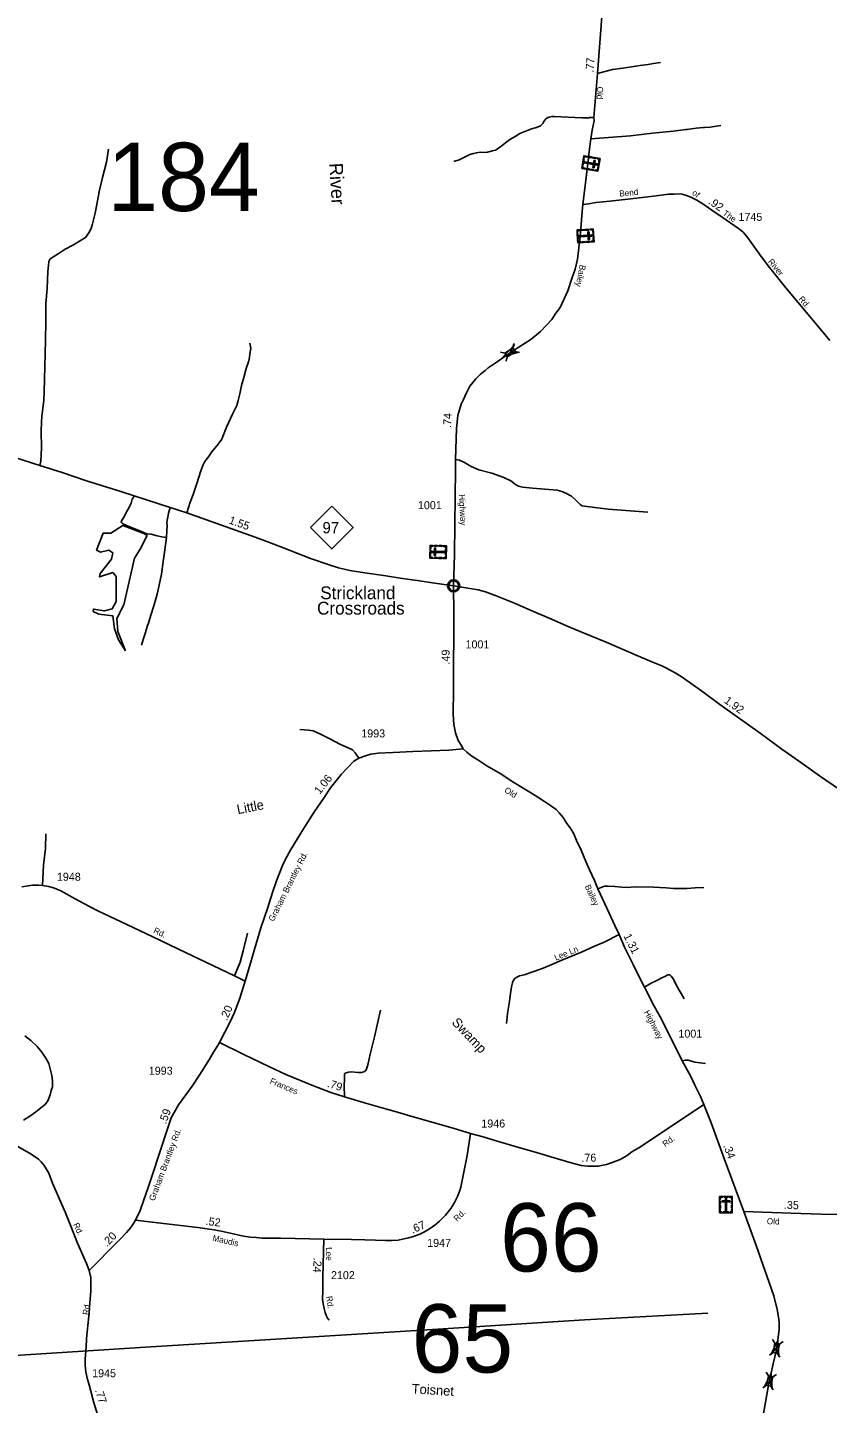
# Model space of a CAD drawing. Extents: x 2220236 to 2384410, y 720751 to 894131.
# Drawn here: x 2285908 to 2298391, y 754902 to 776386 of the extents above; entities that cross this region are included whole.
import ezdxf

# ---------------------------------------------------------------- set-up
doc = ezdxf.new("R2010")
doc.units = 0
doc.layers.add('Default', color=7, linetype='Continuous')

msp = doc.modelspace()

# ---------------------------------------------------------------- linework, layer by layer
at = {"layer": 'Default'}
for p, q in [((2296179, 774794), (2296182, 774794)), ((2296182, 774794), (2296199, 774796)), ((2296199, 774796), (2296201, 774796)), ((2296455, 774824), (2296457, 774824)), ((2296457, 774824), (2296468, 774825)), ((2296468, 774825), (2296471, 774825)), ((2293287, 771316), (2293355, 771302)), ((2293481, 771384), (2293496, 771452)), ((2293519, 771326), (2293587, 771312)), ((2293379, 771175), (2293393, 771243)), ((2297572, 755844), (2297534, 755901)), ((2297640, 755830), (2297697, 755868)), ((2297484, 755657), (2297542, 755696)), ((2297649, 755624), (2297611, 755681)), ((2297380, 755148), (2297438, 755186)), ((2297470, 755334), (2297432, 755391)), ((2297537, 755320), (2297595, 755357)), ((2297545, 755114), (2297507, 755171))]:
    msp.add_line(p, q, dxfattribs=at)
for points in [[(2294572, 773621), (2294615, 773960), (2294663, 774351), (2294685, 774533), (2294700, 774646), (2294721, 774782), (2294748, 774928), (2294747, 774982), (2294801, 775666), (2294954, 777657)], [(2294801, 775666), (2295036, 775729), (2295196, 775754), (2295468, 775795), (2295591, 775810), (2295677, 775825), (2295787, 775839)], [(2292559, 774292), (2292641, 774321), (2292812, 774402), (2292868, 774421), (2292913, 774431), (2292975, 774440), (2293037, 774436), (2293087, 774441), (2293161, 774463), (2293209, 774472), (2293257, 774503), (2293320, 774547), (2293435, 774638), (2293517, 774687), (2293592, 774730), (2293772, 774803), (2293849, 774826), (2293911, 774852), (2293948, 774887), (2293964, 774921), (2293998, 774959), (2294014, 774973), (2294032, 774983), (2294048, 774986), (2294090, 774996), (2294110, 774998), (2294126, 774996), (2294560, 774977), (2294588, 774977), (2294600, 774975), (2294634, 774975), (2294650, 774973), (2294666, 774977), (2294678, 774983), (2294747, 774982)], [(2294700, 774646), (2295316, 774696), (2295659, 774735), (2295983, 774770), (2296179, 774794)], [(2296201, 774796), (2296232, 774800), (2296340, 774815), (2296455, 774824)], [(2296471, 774825), (2296559, 774832), (2296729, 774859)], [(2286097, 769550), (2286117, 769613), (2286127, 769820), (2286118, 770088), (2286125, 770226), (2286132, 770318), (2286148, 770437), (2286162, 770568), (2286169, 770700), (2286174, 770899), (2286178, 771090), (2286183, 771298), (2286188, 771504), (2286193, 771797), (2286195, 772078), (2286214, 772314), (2286226, 772579), (2286233, 772675), (2286239, 772729), (2286255, 772767), (2286286, 772790), (2286319, 772809), (2286387, 772851), (2286497, 772926), (2286626, 772993), (2286745, 773064), (2286813, 773109), (2286865, 773179), (2286902, 773247), (2286923, 773320), (2286961, 773490), (2287033, 773846), (2287078, 774046), (2287138, 774283), (2287172, 774489)], [(2298428, 771502), (2298252, 771715), (2297740, 772321), (2297574, 772532), (2297464, 772666), (2297332, 772847), (2297148, 773105), (2297109, 773156), (2297069, 773198), (2297002, 773247), (2296750, 773424), (2296587, 773532), (2296444, 773633), (2296396, 773664), (2296353, 773691), (2296310, 773712), (2296259, 773736), (2296193, 773763), (2296123, 773784), (2296062, 773789), (2296001, 773787), (2295912, 773786), (2295718, 773759), (2295324, 773714), (2294994, 773677), (2294776, 773654), (2294668, 773635), (2294572, 773621)], [(2293362, 771255), (2293562, 771392), (2293762, 771516), (2293911, 771641), (2294007, 771739), (2294089, 771830), (2294153, 771926), (2294218, 772017), (2294338, 772273), (2294404, 772466), (2294455, 772615), (2294488, 772772), (2294532, 773123), (2294553, 773378), (2294563, 773512), (2294572, 773621)], [(2288394, 768809), (2288422, 768891), (2288446, 768975), (2288490, 769096), (2288547, 769267), (2288612, 769463), (2288641, 769546), (2288676, 769609), (2288732, 769685), (2288783, 769762), (2288880, 769881), (2288938, 769959), (2288957, 770003), (2289011, 770144), (2289107, 770350), (2289172, 770487), (2289194, 770562), (2289219, 770668), (2289249, 770799), (2289282, 770923), (2289320, 771064), (2289357, 771169), (2289371, 771236), (2289379, 771290), (2289390, 771375), (2289379, 771459)], [(2292557, 767669), (2292569, 768152), (2292576, 768630), (2292581, 769037), (2292586, 769500), (2292588, 769642), (2292600, 770127), (2292623, 770328), (2292647, 770418), (2292675, 770507), (2292706, 770569), (2292759, 770682), (2292810, 770784), (2292902, 770899), (2292972, 770971), (2293047, 771032), (2293096, 771074), (2293204, 771146), (2293258, 771184), (2293305, 771215), (2293362, 771255)], [(2284719, 769987), (2285579, 769716), (2286097, 769550), (2286448, 769441), (2286829, 769308), (2287362, 769142), (2287570, 769072), (2288135, 768892), (2288394, 768809), (2289461, 768428), (2289685, 768344), (2289978, 768231), (2290325, 768095), (2290629, 767992), (2290758, 767950), (2290938, 767908), (2291170, 767873), (2291498, 767826), (2291724, 767791), (2291990, 767752), (2292265, 767711), (2292557, 767669)], [(2292588, 769642), (2292651, 769631), (2292724, 769596), (2292831, 769530), (2292951, 769479), (2293152, 769430), (2293342, 769360), (2293448, 769306), (2293523, 769250), (2293570, 769224), (2293633, 769210), (2293790, 769193), (2294174, 769161), (2294247, 769142), (2294307, 769116), (2294396, 769067), (2294481, 768992), (2294532, 768939), (2294565, 768918), (2294635, 768909), (2294970, 768866), (2295586, 768821)], [(2287570, 769072), (2287556, 769043), (2287540, 769022), (2287523, 768962), (2287505, 768920), (2287486, 768882), (2287469, 768852), (2287408, 768743), (2287369, 768675), (2287373, 768656), (2287394, 768637), (2287478, 768598), (2287607, 768546), (2287706, 768508), (2287771, 768483), (2287837, 768474), (2287928, 768448), (2288003, 768434), (2288074, 768424)], [(2288074, 768424), (2288080, 768529), (2288085, 768604), (2288083, 768652), (2288088, 768694), (2288099, 768743), (2288109, 768803), (2288125, 768857), (2288135, 768892)], [(2287436, 766655), (2287319, 766956), (2287299, 767158), (2287410, 767371), (2287579, 768103), (2287667, 768240), (2287772, 768453), (2287723, 768485), (2287394, 768610), (2287209, 768493), (2287088, 768493), (2286984, 768228), (2287048, 768196), (2287177, 768228), (2287241, 768184), (2287217, 768083), (2287040, 767862), (2287032, 767809), (2287237, 767878), (2287289, 767817), (2287292, 767422), (2287229, 767310), (2287108, 767278), (2286935, 767306), (2286931, 767270), (2287020, 767226), (2287239, 767198), (2287267, 766997), (2287327, 766824), (2287436, 766655)], [(2287685, 766743), (2287715, 766846), (2287748, 766939), (2287765, 767000), (2287779, 767047), (2287793, 767085), (2287834, 767212), (2287877, 767354), (2287929, 767539), (2287964, 767678), (2287996, 767853), (2288024, 768048), (2288052, 768233), (2288074, 768424)], [(2292707, 765123), (2292675, 765181), (2292630, 765256), (2292585, 765371), (2292560, 765505), (2292550, 765666), (2292553, 766043), (2292557, 766307), (2292557, 766558), (2292558, 766773), (2292562, 766967), (2292558, 767237), (2292557, 767669)], [(2292557, 767669), (2292941, 767604), (2293056, 767573), (2293221, 767515), (2293508, 767398), (2293766, 767286), (2294048, 767166), (2294357, 767030), (2294680, 766895), (2294935, 766787), (2295443, 766572), (2295676, 766474), (2295805, 766420), (2295870, 766387), (2295938, 766354), (2296015, 766310), (2296109, 766252), (2296423, 766028), (2296712, 765816), (2297339, 765367), (2297679, 765120), (2297992, 764902), (2298265, 764703), (2298578, 764488)], [(2290159, 765425), (2290290, 765416), (2290365, 765406), (2290477, 765352), (2290623, 765280), (2290791, 765193), (2290903, 765144), (2290979, 765107), (2291021, 765062), (2291079, 764977)], [(2289304, 761495), (2289550, 762328), (2289657, 762647), (2289730, 762883), (2289791, 763061), (2289884, 763302), (2289931, 763403), (2290018, 763551), (2290215, 763876), (2290384, 764145), (2290524, 764347), (2290636, 764515), (2290803, 764725), (2290894, 764823), (2291000, 764930), (2291079, 764977), (2291196, 765019), (2291267, 765042), (2291379, 765056), (2291613, 765069), (2291920, 765083), (2292204, 765093), (2292483, 765104), (2292707, 765123)], [(2296461, 759572), (2296407, 759695), (2296373, 759767), (2296322, 759870), (2296257, 760008), (2296125, 760251), (2295805, 760891), (2295680, 761115), (2295533, 761403), (2295467, 761535), (2295359, 761754), (2295221, 762029), (2295139, 762223), (2295071, 762366), (2294954, 762623), (2294809, 762939), (2294755, 763068), (2294685, 763222), (2294619, 763365), (2294549, 763540), (2294472, 763694), (2294431, 763799), (2294373, 763890), (2294326, 763959), (2294265, 764052), (2294206, 764127), (2294157, 764176), (2294068, 764237), (2293973, 764303), (2293869, 764370), (2293745, 764448), (2293499, 764597), (2293281, 764736), (2293075, 764859), (2292934, 764952), (2292839, 765011), (2292763, 765073), (2292707, 765123)], [(2286143, 762992), (2286158, 763306), (2286187, 763570), (2286193, 763799)], [(2289304, 761495), (2289135, 761581), (2288373, 761944), (2287865, 762186), (2287270, 762469), (2287013, 762590), (2286862, 762666), (2286649, 762779), (2286425, 762909), (2286327, 762950), (2286239, 762973), (2286143, 762992), (2286079, 762995), (2285985, 762995), (2285817, 762967)], [(2294809, 762939), (2294912, 762978), (2294968, 762978), (2295074, 762975), (2295184, 762964), (2295264, 762961), (2295322, 762964), (2295398, 762970), (2295678, 762965), (2295872, 762955), (2295986, 762944), (2296198, 762942), (2296324, 762951), (2296460, 762956)], [(2289135, 761581), (2289224, 761791), (2289272, 761971), (2289338, 762244)], [(2293383, 760833), (2293398, 760989), (2293422, 761147), (2293437, 761269), (2293462, 761409), (2293475, 761471), (2293485, 761501), (2293514, 761537), (2293542, 761558), (2293584, 761580), (2293658, 761593), (2293811, 761646), (2293953, 761700), (2294090, 761757), (2294243, 761824), (2294562, 761953), (2294745, 762037), (2294904, 762104), (2295139, 762223)], [(2288903, 760539), (2288989, 760702), (2289067, 760851), (2289139, 761005), (2289221, 761231), (2289304, 761495)], [(2295533, 761403), (2295642, 761463), (2295728, 761508), (2295805, 761548), (2295851, 761570), (2295901, 761593), (2295931, 761595), (2295954, 761572), (2295987, 761525), (2296027, 761448), (2296078, 761355), (2296106, 761301), (2296156, 761219)], [(2290854, 759691), (2290850, 759860), (2290856, 759972), (2290856, 760028), (2290856, 760050), (2290866, 760059), (2290918, 760076), (2290960, 760079), (2291065, 760071), (2291117, 760072), (2291157, 760080), (2291181, 760096), (2291197, 760122), (2291222, 760208), (2291255, 760355), (2291320, 760625), (2291416, 761044)], [(2285864, 760642), (2285959, 760567), (2286056, 760474), (2286131, 760385), (2286194, 760293), (2286240, 760208), (2286288, 760022), (2286297, 759936), (2286298, 759848), (2286278, 759788), (2286261, 759720), (2286222, 759630), (2286181, 759569), (2286117, 759517), (2286032, 759450), (2285942, 759389), (2285847, 759328)], [(2287594, 757762), (2287663, 757915), (2287715, 758065), (2287797, 758292), (2287853, 758463), (2288085, 759177), (2288151, 759362), (2288261, 759566), (2288477, 759857), (2288594, 760037), (2288748, 760278), (2288811, 760385), (2288865, 760475), (2288903, 760539)], [(2288903, 760539), (2289282, 760351), (2289671, 760164), (2289941, 760038), (2290369, 759860), (2290639, 759757), (2290854, 759691), (2291164, 759595), (2291419, 759523), (2291683, 759448), (2291888, 759390), (2292236, 759288), (2292548, 759199), (2292820, 759119)], [(2296125, 760251), (2296172, 760265), (2296219, 760260), (2296320, 760230), (2296402, 760220), (2296489, 760213)], [(2292820, 759119), (2293016, 759063), (2293171, 759019), (2293448, 758937), (2293900, 758805), (2294124, 758737), (2294390, 758657), (2294547, 758619), (2294652, 758605), (2294738, 758605), (2294814, 758607), (2294940, 758633), (2295033, 758664), (2295156, 758710), (2295265, 758774), (2295339, 758832), (2295472, 758911), (2296461, 759572)], [(2297087, 757898), (2296761, 758769), (2296575, 759285), (2296461, 759572)], [(2290532, 757469), (2290965, 757463), (2291171, 757456), (2291337, 757452), (2291492, 757449), (2291594, 757449), (2291694, 757452), (2291854, 757487), (2291932, 757511), (2292028, 757548), (2292103, 757581), (2292182, 757630), (2292262, 757686), (2292339, 757750), (2292429, 757841), (2292511, 757944), (2292567, 758030), (2292618, 758134), (2292656, 758225), (2292670, 758279), (2292696, 758410), (2292728, 758564), (2292770, 758773), (2292820, 759119)], [(2286868, 756978), (2286828, 757087), (2286689, 757404), (2286583, 757671), (2286499, 757881), (2286299, 758343), (2286239, 758497), (2286169, 758619), (2286122, 758674), (2286079, 758715), (2285966, 758796), (2285718, 758934)], [(2286868, 756978), (2286930, 757042), (2287045, 757157), (2287141, 757255), (2287371, 757485), (2287453, 757574), (2287519, 757652), (2287560, 757713), (2287594, 757762)], [(2287594, 757762), (2287853, 757735), (2288339, 757677), (2288567, 757651), (2288818, 757614), (2288954, 757586), (2289278, 757515), (2289388, 757498), (2289476, 757491), (2289570, 757484), (2289714, 757484), (2289862, 757481), (2290532, 757469)], [(2297593, 755740), (2297602, 755781), (2297629, 755975), (2297637, 756070), (2297636, 756150), (2297631, 756216), (2297605, 756371), (2297553, 756581), (2297278, 757371), (2297087, 757898)], [(2297087, 757898), (2297820, 757876), (2298292, 757859), (2298541, 757853), (2298725, 757842), (2298931, 757827)], [(2290532, 757469), (2290516, 756878), (2290514, 756659), (2290512, 756532), (2290519, 756456), (2290535, 756384), (2290552, 756321), (2290572, 756265), (2290590, 756232), (2290614, 756201)], [(2287167, 754200), (2287109, 754392), (2287067, 754530), (2287001, 754731), (2286937, 754931), (2286870, 755191), (2286839, 755296), (2286815, 755396), (2286813, 755443), (2286806, 755503), (2286807, 755601), (2286821, 755780), (2286830, 755912), (2286851, 756119), (2286870, 756313), (2286881, 756471), (2286894, 756654), (2286896, 756785), (2286893, 756867), (2286868, 756978)], [(2296526, 756314), (2294600, 756208), (2292309, 756063), (2290035, 755921), (2287749, 755780), (2285466, 755635), (2283160, 755491), (2281790, 755396), (2279029, 755228), (2276729, 755065), (2274892, 754928), (2272866, 754783), (2271512, 753789), (2270402, 752966), (2269282, 752170), (2268166, 751348), (2267047, 750534), (2265929, 749726), (2264444, 748641), (2263328, 747822), (2262406, 747872), (2261484, 747927), (2260116, 748002), (2259542, 748037)], [(2297473, 755187), (2297546, 755521), (2297593, 755740)], [(2295911, 751310), (2295991, 751430), (2296084, 751583), (2296202, 751770), (2296322, 751957), (2296447, 752132), (2296567, 752337), (2296624, 752443), (2296903, 752934), (2296944, 753012), (2297041, 753243), (2297107, 753406), (2297133, 753488), (2297148, 753546), (2297169, 753645), (2297209, 753859), (2297244, 754069), (2297387, 754714), (2297473, 755187)]]:
    msp.add_lwpolyline(points, dxfattribs=at)
for points in [[(2294842, 774341), (2294809, 774145), (2294558, 774187), (2294591, 774383)], [(2294592, 774325), (2294578, 774241), (2294567, 774243), (2294581, 774327)], [(2294585, 774351), (2294596, 774349), (2294600, 774370), (2294640, 774364), (2294642, 774375), (2294591, 774383)], [(2294660, 774372), (2294702, 774365), (2294700, 774353), (2294658, 774361)], [(2294726, 774361), (2294769, 774354), (2294767, 774342), (2294724, 774350)], [(2294768, 774312), (2294749, 774315), (2294730, 774199), (2294749, 774196)], [(2294799, 774349), (2294797, 774337), (2294829, 774332), (2294822, 774292), (2294833, 774290), (2294842, 774341)], [(2294563, 774220), (2294575, 774218), (2294571, 774196), (2294611, 774189), (2294609, 774178), (2294558, 774187)], [(2294795, 774239), (2294798, 774257), (2294598, 774290), (2294595, 774272)], [(2294631, 774186), (2294674, 774179), (2294672, 774168), (2294629, 774175)], [(2294696, 774175), (2294739, 774168), (2294737, 774157), (2294694, 774164)], [(2294766, 774152), (2294768, 774163), (2294800, 774158), (2294806, 774198), (2294817, 774196), (2294809, 774145)], [(2294830, 774268), (2294821, 774217), (2294810, 774219), (2294818, 774270)], [(2294737, 773239), (2294748, 773040), (2294494, 773026), (2294483, 773225)], [(2294553, 773229), (2294596, 773231), (2294596, 773220), (2294553, 773218)], [(2294620, 773233), (2294663, 773235), (2294664, 773224), (2294620, 773221)], [(2294694, 773237), (2294694, 773226), (2294727, 773227), (2294729, 773187), (2294740, 773187), (2294737, 773239)], [(2294485, 773192), (2294496, 773193), (2294495, 773215), (2294535, 773217), (2294535, 773228), (2294483, 773225)], [(2294497, 773168), (2294502, 773084), (2294491, 773083), (2294486, 773168)], [(2294492, 773059), (2294503, 773060), (2294505, 773038), (2294545, 773040), (2294546, 773029), (2294494, 773026)], [(2294714, 773129), (2294713, 773147), (2294510, 773136), (2294511, 773118)], [(2294565, 773042), (2294609, 773044), (2294609, 773033), (2294566, 773030)], [(2294631, 773045), (2294674, 773048), (2294675, 773036), (2294632, 773034)], [(2294671, 773195), (2294653, 773194), (2294659, 773076), (2294678, 773077)], [(2294705, 773038), (2294704, 773049), (2294736, 773051), (2294734, 773092), (2294745, 773092), (2294748, 773040)], [(2294741, 773165), (2294744, 773114), (2294733, 773113), (2294730, 773165)], [(2293568, 771319), (2293334, 771249), (2293502, 771427), (2293438, 771313)], [(2293355, 771302), (2293481, 771384), (2293520, 771325), (2293393, 771243)], [(2290323, 768579), (2290656, 768912), (2290989, 768579), (2290656, 768246)], [(2292186, 768101), (2292190, 768300), (2292445, 768295), (2292441, 768096)], [(2292233, 768299), (2292233, 768288), (2292201, 768289), (2292200, 768248), (2292189, 768248), (2292190, 768300)], [(2292306, 768287), (2292263, 768287), (2292263, 768299), (2292306, 768298)], [(2292372, 768285), (2292329, 768286), (2292329, 768298), (2292372, 768297)], [(2292444, 768262), (2292432, 768262), (2292433, 768284), (2292392, 768285), (2292393, 768296), (2292445, 768295)], [(2292229, 768100), (2292230, 768112), (2292197, 768112), (2292198, 768153), (2292187, 768153), (2292186, 768101)], [(2292188, 768175), (2292189, 768227), (2292200, 768227), (2292199, 768175)], [(2292217, 768210), (2292217, 768191), (2292420, 768187), (2292420, 768206)], [(2292255, 768141), (2292274, 768140), (2292276, 768258), (2292257, 768258)], [(2292304, 768099), (2292260, 768100), (2292260, 768111), (2292304, 768110)], [(2292371, 768098), (2292327, 768098), (2292328, 768110), (2292371, 768109)], [(2292441, 768129), (2292430, 768130), (2292429, 768108), (2292389, 768108), (2292389, 768097), (2292441, 768096)], [(2292430, 768154), (2292432, 768239), (2292443, 768239), (2292442, 768154)], [(2292479, 767681), (2292480, 767687), (2292482, 767693), (2292485, 767700), (2292488, 767706), (2292491, 767712), (2292495, 767717), (2292499, 767721), (2292503, 767726), (2292509, 767731), (2292514, 767734), (2292519, 767737), (2292524, 767740), (2292530, 767742), (2292535, 767744), (2292540, 767745), (2292544, 767746), (2292549, 767746), (2292555, 767747), (2292559, 767746), (2292565, 767746), (2292570, 767745), (2292575, 767744), (2292580, 767743), (2292585, 767741), (2292592, 767738), (2292598, 767735), (2292603, 767731), (2292608, 767727), (2292612, 767724), (2292616, 767720), (2292620, 767715), (2292623, 767710), (2292626, 767705), (2292628, 767700), (2292630, 767695), (2292632, 767690), (2292633, 767686), (2292634, 767680), (2292635, 767675), (2292635, 767669), (2292635, 767663), (2292634, 767657), (2292633, 767652), (2292632, 767646), (2292630, 767640), (2292628, 767635), (2292624, 767629), (2292621, 767623), (2292618, 767619), (2292613, 767614), (2292608, 767609), (2292603, 767605), (2292598, 767602), (2292594, 767599), (2292587, 767596), (2292580, 767593), (2292574, 767592), (2292567, 767590), (2292563, 767590), (2292558, 767590), (2292553, 767590), (2292548, 767590), (2292543, 767591), (2292537, 767592), (2292532, 767593), (2292527, 767595), (2292523, 767597), (2292519, 767599), (2292512, 767603), (2292506, 767608), (2292501, 767612), (2292497, 767617), (2292494, 767621), (2292491, 767625), (2292487, 767632), (2292485, 767636), (2292483, 767640), (2292481, 767648), (2292479, 767655), (2292478, 767660), (2292478, 767667), (2292478, 767671), (2292479, 767678)], [(2296707, 758135), (2296906, 758135), (2296906, 757880), (2296707, 757880)], [(2296707, 758092), (2296719, 758092), (2296719, 758124), (2296759, 758124), (2296759, 758135), (2296707, 758135)], [(2296707, 758018), (2296707, 758061), (2296719, 758061), (2296719, 758018)], [(2296707, 757950), (2296707, 757994), (2296719, 757994), (2296719, 757950)], [(2296748, 758067), (2296748, 758048), (2296866, 758048), (2296866, 758067)], [(2296781, 758135), (2296833, 758135), (2296833, 758124), (2296781, 758124)], [(2296816, 758106), (2296798, 758106), (2296798, 757903), (2296816, 757903)], [(2296906, 758092), (2296895, 758092), (2296895, 758124), (2296854, 758124), (2296854, 758135), (2296906, 758135)], [(2296895, 758019), (2296895, 758062), (2296906, 758062), (2296906, 758019)], [(2296895, 757953), (2296895, 757996), (2296906, 757996), (2296906, 757953)], [(2296740, 757881), (2296740, 757892), (2296718, 757892), (2296718, 757932), (2296707, 757932), (2296707, 757881)], [(2296765, 757892), (2296849, 757892), (2296849, 757881), (2296765, 757881)], [(2296873, 757880), (2296873, 757892), (2296895, 757892), (2296895, 757932), (2296906, 757932), (2296906, 757880)], [(2297508, 755665), (2297617, 755883), (2297631, 755639), (2297592, 755763)], [(2297542, 755696), (2297572, 755844), (2297641, 755830), (2297611, 755681)], [(2297404, 755155), (2297514, 755373), (2297528, 755129), (2297489, 755253)], [(2297438, 755186), (2297469, 755334), (2297538, 755319), (2297507, 755171)]]:
    msp.add_lwpolyline(points, close=True, dxfattribs=at)
for centre, radius in [((2292557, 767669), 94.3), ((2292556, 767669), 76.7)]:
    msp.add_circle(centre, radius, dxfattribs=at)

# ---------------------------------------------------------------- texts
for s, height, rotation, p in [('.77', 125, 85.5962, (2294739, 775680)), ('Old', 95, 267.9136, (2294797, 775465)), ('River', 210, 273.3951, (2290616, 774266)), ('Bend', 95, 5.7449, (2295147, 773745)), ('of', 95, 320.2607, (2296269, 773789)), ('.92', 125, 324.8431, (2296522, 773644)), ('The', 95, 324.8431, (2296747, 773467)), ('Bailey', 95, 258.6727, (2294528, 772688)), ('River', 95, 309.0618, (2297456, 772728)), ('Rd.', 95, 310.2004, (2297933, 772143)), ('.74', 125, 86.9586, (2292517, 770131)), ('Highway', 95, 272.9847, (2292638, 769096)), ('1.55', 125, 340.3651, (2289039, 768645)), ('.49', 125, 89.5345, (2292493, 766440)), ('1.92', 125, 324.3673, (2296768, 765852)), ('1.06', 125, 51.474, (2290468, 764405)), ('Old', 95, 328.3955, (2293339, 764453)), ('Little', 150, 11.0996, (2289190, 764102)), ('Graham Brantley Rd. ', 95, 63.3244, (2289747, 762420)), ('Bailey', 95, 295.2917, (2294600, 762976)), ('Rd.', 95, 334.4962, (2287863, 762255)), ('1.31', 125, 296.5504, (2295205, 762201)), ('Lee Ln', 95, 22.3063, (2294152, 761815)), ('.20', 125, 66.3947, (2289019, 760871)), ('Highway', 95, 297.3577, (2295524, 761012)), ('Swamp', 150, 313.4885, (2292518, 760841)), ('Frances', 95, 337.2738, (2289680, 759901)), ('.79', 125, 342.2072, (2290575, 759848)), ('.59', 125, 69.4239, (2288068, 759257)), ('Graham Brantley Rd. ', 95, 69.3629, (2287887, 758057)), ('Rd.', 95, 35.9056, (2295859, 758904)), ('.34', 125, 290.525, (2296762, 758927)), ('.76', 125, 1.303, (2294552, 758674)), ('.35', 125, 357.9654, (2297709, 757942)), ('.52', 125, 352.988, (2288682, 757691)), ('Rd.', 95, 44.8993, (2292613, 757735)), ('Old', 95, 358.1284, (2297444, 757702)), ('Rd.', 95, 294.4378, (2286617, 757697)), ('.20', 125, 46.1181, (2287148, 757340)), ('.67', 125, 23.8524, (2291917, 757552)), ('Maudis', 95, 347.0465, (2288788, 757445)), ('Lee', 95, 270.8217, (2290564, 757342)), ('.24', 125, 266.8253, (2290375, 757181)), ('Rd.', 95, 278.4568, (2290566, 756572)), ('Rd.', 95, 82.2413, (2286861, 756279)), ('Toisnet', 150, 356.3782, (2291900, 755060)), ('.77', 125, 288.7287, (2286957, 755108))]:
    msp.add_text(s, height=height, rotation=rotation, dxfattribs=at).set_placement(p)
for s, height, p in [('184', 1066.3, (2287152, 773521)), ('1745', 125, (2297002, 773367)), ('1001', 125, (2292000, 768866)), ('97', 175, (2290510, 768490)), ('Strickland', 200, (2290475, 767460)), ('Crossroads', 200, (2290425, 767220)), ('1001', 125, (2292742, 766692)), ('1993', 125, (2291116, 765302)), ('1948', 125, (2286366, 763064)), ('1001', 125, (2296065, 760614)), ('1993', 125, (2287800, 760035)), ('1946', 125, (2292989, 759211)), ('66', 1066.3, (2293282, 756963)), ('1947', 125, (2292144, 757347)), ('2102', 125, (2290643, 756843)), ('65', 1066.3, (2291901, 755385)), ('1945', 125, (2286916, 755312))]:
    msp.add_text(s, height=height, dxfattribs=at).set_placement(p)

doc.saveas('drawing.dxf')
